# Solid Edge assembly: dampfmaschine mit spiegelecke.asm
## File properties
Author: ra-tv
Template: Normal.asm
Last saved by: ra-11
Revision: 16
Application: Solid Edge
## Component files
Grundplatte.par
Kurbenwellenhalter.par
Kurbelwelle.par
Pleuel1.par
Kolben.par
Kurbelwellenplatte 1.par
Kurbelwellenplatte2.par
rper mit zwei Bohrungen.par
Pleuel2.par
Stift 1mm.par
Chromecke.par
Stift 3mm.par
